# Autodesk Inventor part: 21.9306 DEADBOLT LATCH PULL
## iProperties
Created: 2012-07
Part Number: 21.9306 DEADBOLT LATCH PULL
Document SubType Name: Modeling
Designer: Administrator
Density: 1.13 g/cm^3
Material: Nylon-6/6
Mass: 2.11751 g
Surface Area: 13.7326 cm^2
Volume: 1.8739 cm^3
Author: Administrator
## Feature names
1. Base1
